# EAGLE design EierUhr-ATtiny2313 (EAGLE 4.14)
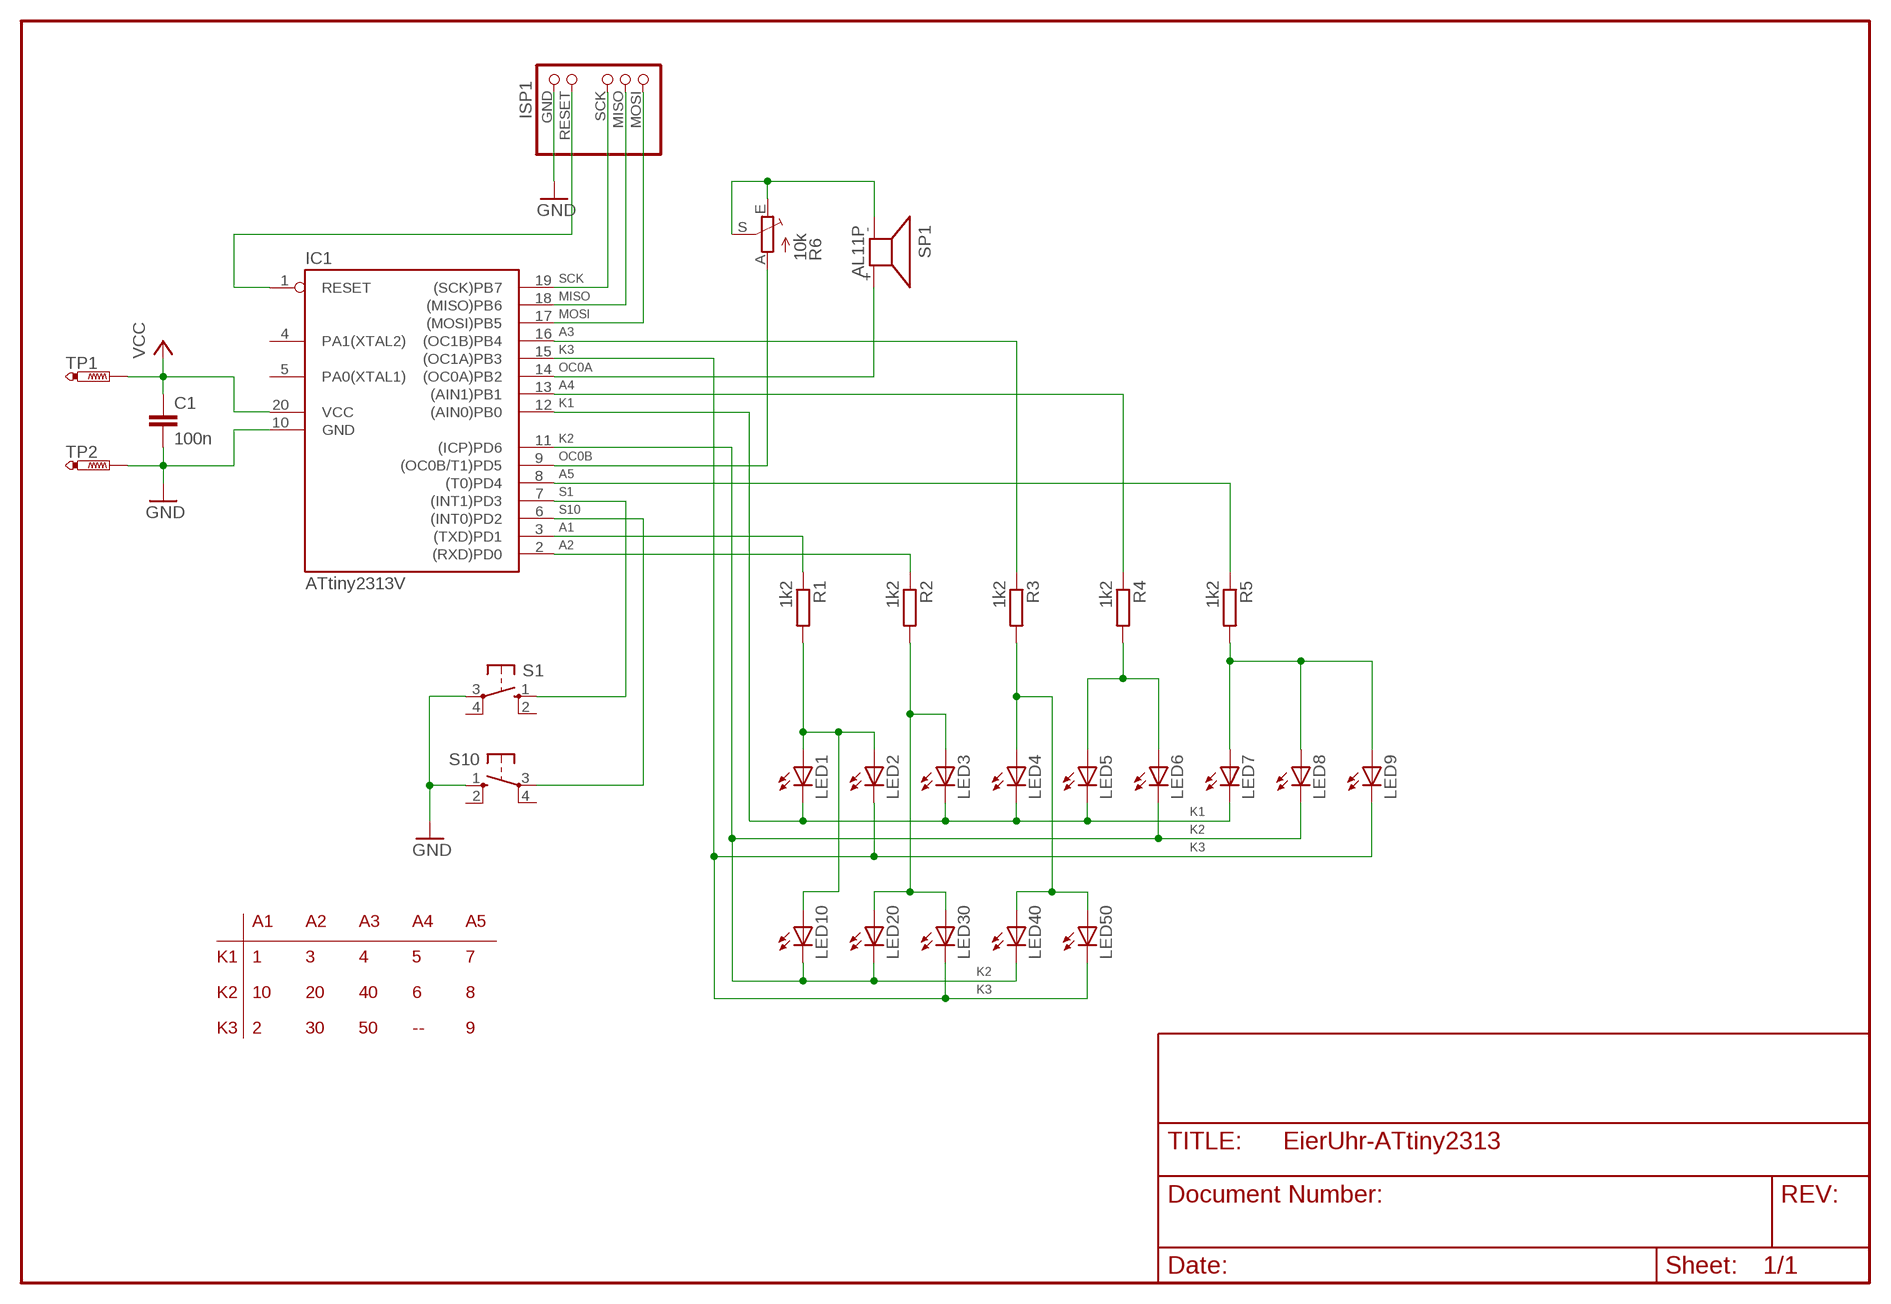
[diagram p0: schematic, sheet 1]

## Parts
C1  100n  C-EU050-024X044  [C050-024X044]
IC1  ATtiny2313V  AT90S2313P  [DIL20]
ISP1  ISP  [PINHD6.ISP]
LED1  LED3MM  [LED3MM]
LED2  LED3MM  [LED3MM]
LED3  LED3MM  [LED3MM]
LED4  LED3MM  [LED3MM]
LED5  LED3MM  [LED3MM]
LED6  LED3MM  [LED3MM]
LED7  LED3MM  [LED3MM]
LED8  LED3MM  [LED3MM]
LED9  LED3MM  [LED3MM]
LED10  LED3MM  [LED3MM]
LED20  LED3MM  [LED3MM]
LED30  LED3MM  [LED3MM]
LED40  LED3MM  [LED3MM]
LED50  LED3MM  [LED3MM]
R1  1k2  R-EU_0204/5  [0204/5]
R2  1k2  R-EU_0204/5  [0204/5]
R3  1k2  R-EU_0204/5  [0204/5]
R4  1k2  R-EU_0204/5  [0204/5]
R5  1k2  R-EU_0204/5  [0204/5]
R6  10k  TRIM_EU-S75H  [S75H]
S1  10-XX  [B3F-10XX]
S10  10-XX  [B3F-10XX]
SP1  AL11P  [AL11P]
TP1  PTR1PAD1-13  [P1-13]
TP2  PTR1PAD1-13  [P1-13]

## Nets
A1: IC1.3((TXD)PD1) R1.1
A1.R: LED1.A LED2.A LED10.A R1.2
A2: IC1.2((RXD)PD0) R2.1
A2.R: LED3.A LED20.A LED30.A R2.2
A3: IC1.16((OC1B)PB4) R3.1
A3.R: LED4.A LED40.A LED50.A R3.2
A4: IC1.13((AIN1)PB1) R4.1
A4.R: LED5.A LED6.A R4.2
A5: IC1.8((T0)PD4) R5.1
A5.R: LED7.A LED8.A LED9.A R5.2
GND: C1.2 IC1.10(GND) ISP1.GND S1.3(P) S10.1(S) TP2.1(TP)
K1: IC1.12((AIN0)PB0) LED1.K(C) LED3.K(C) LED4.K(C) LED5.K(C) LED7.K(C)
K2: IC1.11((ICP)PD6) LED6.K(C) LED8.K(C) LED10.K(C) LED20.K(C) LED40.K(C)
K3: IC1.15((OC1A)PB3) LED2.K(C) LED9.K(C) LED30.K(C) LED50.K(C)
MISO: IC1.18((MISO)PB6) ISP1.MISO
MOSI: IC1.17((MOSI)PB5) ISP1.MOSI
OC0A: IC1.14((OC0A)PB2) SP1.+
OC0B: IC1.9((OC0B/T1)PD5) R6.A
RESET: IC1.1(RESET) ISP1.RESET
S1: IC1.7((INT1)PD3) S1.1(S)
S10: IC1.6((INT0)PD2) S10.3(P)
SCK: IC1.19((SCK)PB7) ISP1.SCK
SPK: R6.E R6.S SP1.-
VCC: C1.1 IC1.20(VCC) TP1.1(TP)
Unconnected: IC1.4(PA1(XTAL2)) IC1.5(PA0(XTAL1)) S1.2(S1) S1.4(P1) S10.2(S1) S10.4(P1)

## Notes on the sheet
- A1 | A2 | A3 | A4 | A5
- K1 | 1 | 3 | 4 | 5 | 7
- K2 | 10 | 20 | 40 | 6 | 8
- K3 | 2 | 30 | 50 | -- | 9

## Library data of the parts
C1 = rcl:C-EU: CAPACITOR, European symbol
IC1 = atmel-gjl:AT90S2313: MICROCONTROLLER 2 Kbytes FLASH 128 bytes SRAM 128 bytes EEPROM UART
ISP1 = eigene:ISP
LED1-LED10 LED20 LED30 LED40 LED50 = led:LED: LED
R1-R5 = rcl:R-EU_: RESISTOR, European symbol
R6 = pot:TRIM_EU-: POTENTIOMETER
S1 S10 = switch-omron:10-XX: OMRON SWITCH
SP1 = buzzer:AL11P: SPEAKER
TP1 TP2 = testpad:PTR1: TEST PIN

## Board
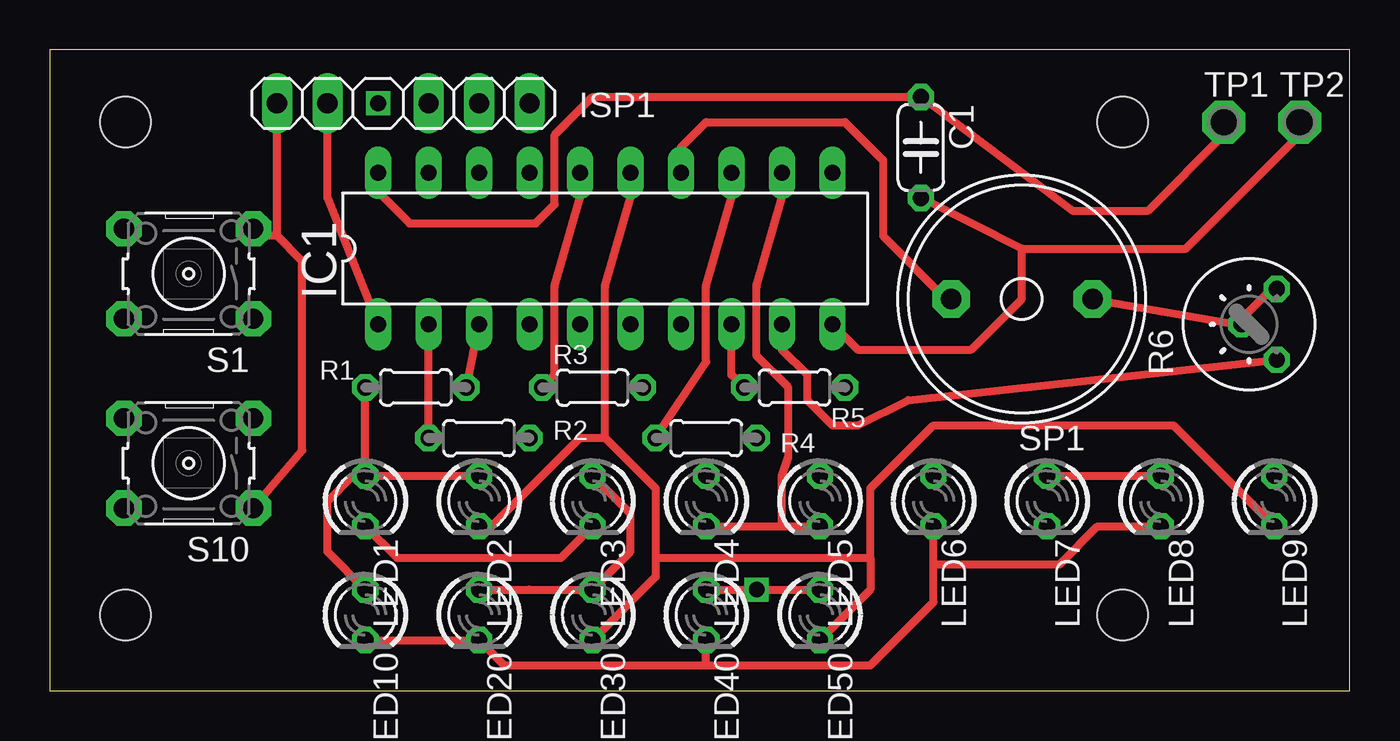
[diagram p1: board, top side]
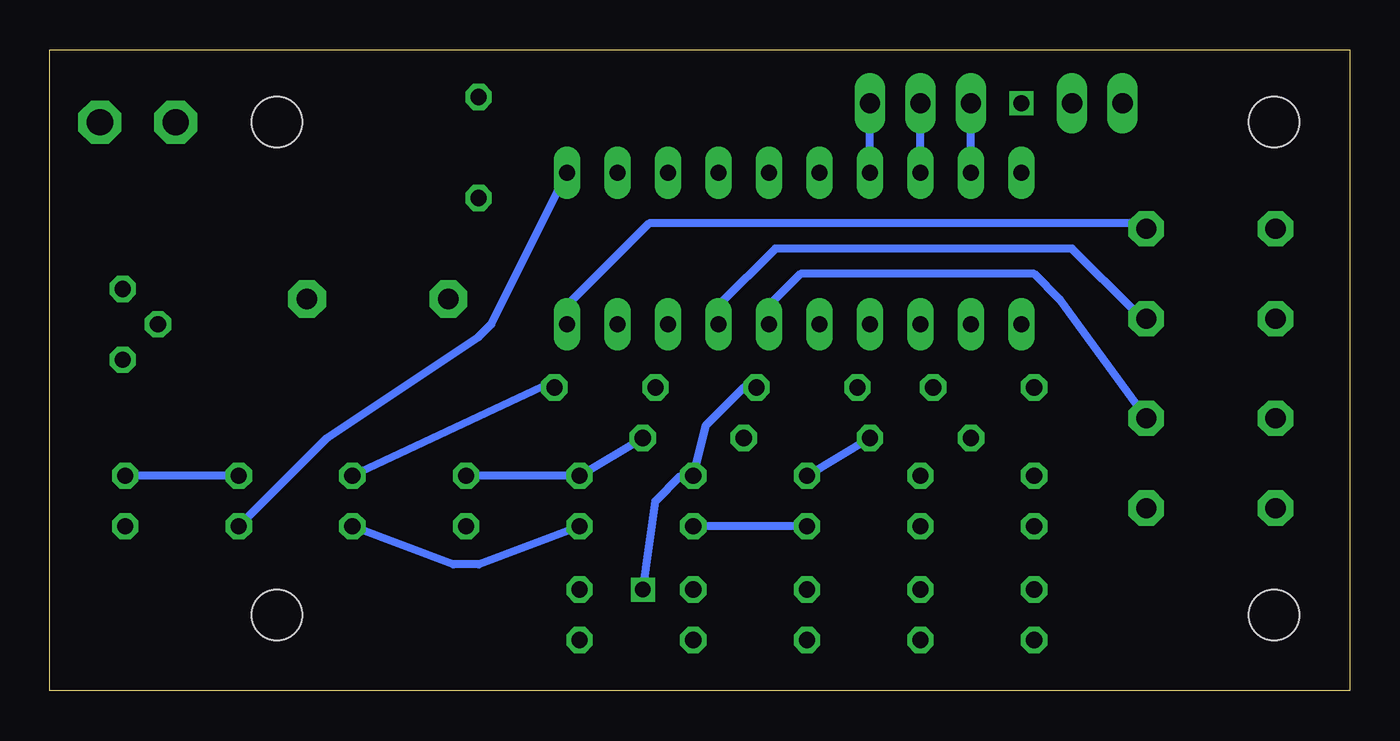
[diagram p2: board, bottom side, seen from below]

Size 65.39 x 32.24 mm. Coordinates in mm from the lower left corner, seen from the top.
Outline: 0,0 65.39,0 65.39,32.24 0,32.24 0,0
Copper layers (1+16): Top 0.035mm / dielectric 1.5mm / Bottom 0.035mm
Design rules "default": minimum track width 10mil, minimum drill 24mil, track to track 8mil, track to pad 8mil, pad to pad 8mil, via to via 8mil, smd to smd 8mil, copper to edge 40mil, drill to drill 8mil, minimum pad ring 10mil, minimum via ring 8mil, stop-mask expansion 4mil, vias tented up to drill 0mil, thermal gap 10mil
vRestrict: area 58.3,-0.4 to 65.4,32.2

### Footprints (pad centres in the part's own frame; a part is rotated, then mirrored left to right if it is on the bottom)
C050-024X044 = drill 0.813 octagon: 1 -2.54,0; 2 2.54,0
DIL20 = drill 0.813 long: 1 -11.43,-3.81; 2 -8.89,-3.81; 3 -6.35,-3.81; 4 -3.81,-3.81; 5 -1.27,-3.81; 6 1.27,-3.81; 7 3.81,-3.81; 8 6.35,-3.81; 9 8.89,-3.81; 10 11.43,-3.81; 11 11.43,3.81; 12 8.89,3.81; 13 6.35,3.81; 14 3.81,3.81; 15 1.27,3.81; 16 -1.27,3.81; 17 -3.81,3.81; 18 -6.35,3.81; 19 -8.89,3.81; 20 -11.43,3.81
PINHD6.ISP = drill 1.016 long: GND -6.35,0; MISO 3.81,0; MOSI 6.35,0; RESET -3.81,0; SCK 1.27,0
LED3MM = drill 0.813 octagon: A -1.27,0; K 1.27,0
0204/5 = drill 0.813 octagon: 1 -2.54,0; 2 2.54,0
S75H = drill 0.813 octagon: A -1.778,-1.397; E 1.778,-1.397; S 0,0.381
B3F-10XX = drill 1.016 pad 1.778 octagon: 1 -3.251,2.261; 2 3.251,2.261; 3 -3.251,-2.261; 4 3.251,-2.261
AL11P = drill 1.016 pad 1.905 octagon: + 3.556,0; - -3.556,0
P1-13 = drill 1.321 pad 2.159 octagon: 1 0,0
BOHRUNG_2MM = hole 2.54: 0,0

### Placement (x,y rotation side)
C1  43.82,27.33 270 top
IC1  27.94,22.25 0 top
ISP1  17.78,29.55 0 top
LED1  15.88,9.55 270 top
LED2  21.59,9.55 270 top
LED3  27.31,9.55 270 top
LED4  33.02,9.55 270 top
LED5  38.74,9.55 270 top
LED6  44.45,9.55 270 top
LED7  50.17,9.55 270 top
LED8  55.88,9.55 270 top
LED9  61.6,9.55 270 top
LED10  15.88,3.83 270 top
LED20  21.59,3.83 270 top
LED30  27.31,3.83 270 top
LED40  33.02,3.83 270 top
LED50  38.74,3.83 270 top
R1  18.42,15.26 180 top
R2  21.59,12.72 0 top
R3  27.31,15.26 0 top
R4  33.02,12.72 0 top
R5  37.47,15.26 0 top
R6  60.33,18.44 90 top
S1  6.99,20.98 180 top
S10  6.99,11.45 180 top
SP1  48.9,19.71 180 top
TP1  59.06,28.6 0 top
TP2  62.87,28.6 0 top
U$1  [BOHRUNG_2MM]  3.81,28.6 0 top
U$2  [BOHRUNG_2MM]  3.81,3.83 0 top
U$3  [BOHRUNG_2MM]  53.98,3.83 0 top
U$4  [BOHRUNG_2MM]  53.98,28.6 0 top

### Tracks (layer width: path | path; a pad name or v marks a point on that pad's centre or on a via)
A1
  Top 0.406: R1.1 IC1.3
A1.R
  Top 0.406: LED1.A R1.2 | LED1.A LED2.A | LED10.A 13.97,7.01 13.97,9.55 15.24,10.82 LED1.A
A2
  Top 0.406: R2.1 IC1.2
A2.R
  Top 0.406: LED20.A 24.13,5.1 LED30.A 29.21,7.01 29.21,8.91 LED3.A
  Bottom 0.406: LED3.A R2.2
A3
  Top 0.406: IC1.16 26.67,24.79 25.4,20.34 25.4,15.9 R3.1
A3.R  (via drill 0.8)
  Top 0.406: LED50.A v35.56,5.1 LED40.A
  Bottom 0.406: v35.56,5.1 34.93,9.55 33.66,10.82 LED4.A 32.39,13.36 30.48,15.26 R3.2
A4
  Top 0.406: IC1.13 34.29,24.79 33.02,20.34 33.02,16.53 R4.1
A4.R
  Bottom 0.406: LED6.A LED5.A R4.2
A5
  Top 0.406: IC1.8 34.29,15.9 R5.1
A5.R
  Top 0.406: LED7.A LED8.A
  Bottom 0.406: LED8.A LED9.A | R5.2 40.64,15.26 LED7.A
GND
  Top 0.406: S10.1 12.7,12.09 12.7,21.61 11.43,22.88 | TP2.1 62.87,27.96 57.15,22.25 48.9,22.25 | 48.9,22.25 C1.2 | IC1.10 40.64,17.17 46.36,17.17 48.9,19.71 48.9,22.25 | S1.3 10.24,22.8 10.16,22.88 11.43,22.88 | 11.43,22.88 ISP1.GND
  Bottom 0.406: IC1.10 39.37,19.39 35.24,23.52 10.8,23.52 10.16,22.88 10.24,22.8 S1.3
K1
  Top 0.406: LED1.K 17.46,6.69 25.72,6.69 LED3.K | LED4.K 36.83,8.28 | 36.83,8.28 LED5.K | IC1.12 36.83,24.79 35.56,20.34 35.56,16.85 37.15,15.26 37.15,11.77 36.83,10.82 36.83,8.28
  Bottom 0.406: LED3.K LED4.K | LED7.K 45.09,6.37 43.82,6.37 LED5.K
K2
  Top 0.406: LED10.K LED20.K 22.86,1.29 33.02,1.29 | 44.45,6.37 44.45,4.47 41.28,1.29 33.02,1.29 | 44.45,6.37 LED6.K | 44.45,6.37 50.8,6.37 52.71,8.28 LED8.K | 33.02,1.29 LED40.K
  Bottom 0.406: LED8.K 51.44,12.72 43.82,17.8 43.18,18.44 IC1.11
K3
  Top 0.406: LED2.K 22.23,8.28 26.67,12.72 27.94,12.72 | LED9.K 56.52,13.36 44.45,13.36 41.28,10.18 41.28,6.69 | 30.48,6.69 30.48,10.18 27.94,12.72 | 30.48,6.69 30.48,5.74 LED30.K | LED50.K 41.28,5.1 41.28,6.69 | 30.48,6.69 41.28,6.69 | 27.94,12.72 27.94,20.34 29.21,24.79 IC1.15
MISO
  Bottom 0.406: IC1.18 ISP1.MISO
MOSI
  Bottom 0.406: IC1.17 ISP1.MOSI
N$20  (via drill 0.8)
  other vias: 16.51,29.55
OC0A
  Top 0.406: IC1.14 31.75,27.33 33.02,28.6 40.01,28.6 41.91,26.69 41.91,22.88 45.09,19.71 SP1.+
OC0B
  Top 0.406: IC1.9 36.83,17.17 38.1,15.9 38.1,14.63 39.37,13.36 40.64,13.36 43.18,14.63 R6.A
RESET
  Top 0.406: ISP1.RESET 13.97,24.79 IC1.1
S1
  Bottom 0.406: IC1.7 31.75,19.39 28.89,22.25 13.97,22.25 10.8,19.07 10.24,18.36 | 10.24,18.36 10.16,18.44 | S1.1 10.24,18.36
S10
  Bottom 0.406: IC1.6 29.21,19.39 27.62,20.98 15.88,20.98 14.61,19.71 S10.3
SCK
  Bottom 0.406: IC1.19 ISP1.SCK
SPK
  Top 0.406: SP1.- 59.69,18.44 | 59.69,18.44 R6.S | R6.E 61.47,20.21 59.69,18.44
VCC
  Top 0.406: TP1.1 59.06,27.96 55.25,24.15 51.44,24.15 C1.1 27.31,29.87 25.4,27.96 25.4,24.47 24.45,23.52 18.1,23.52 16.51,25.1 IC1.20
